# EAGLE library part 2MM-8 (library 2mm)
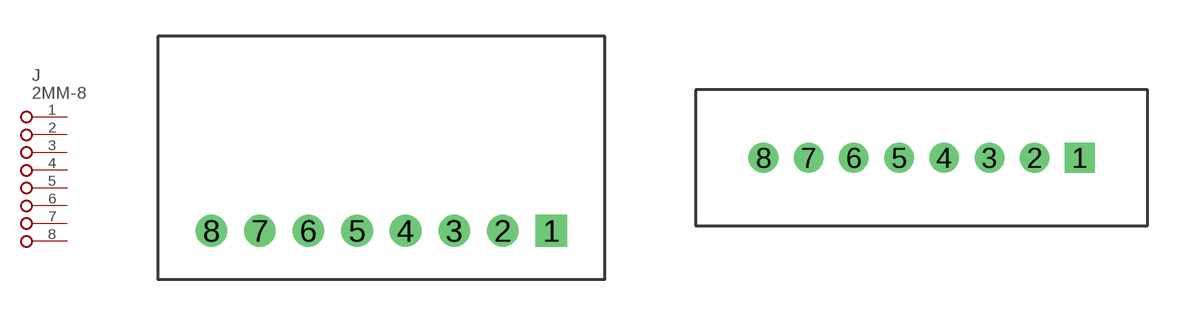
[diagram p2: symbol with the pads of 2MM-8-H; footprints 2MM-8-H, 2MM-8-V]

Designator prefix J

## 2MM-8H  [2MM-8-H]
1  1
2  2
3  3
4  4
5  5
6  6
7  7
8  8

## 2MM-8V  [2MM-8-V]
Pads as for 2MM-8-H

## Footprint 2MM-8-H (pad centres in mm)
drill 0.8 square: 1 0,0
drill 0.8 round: 2 -2,0; 3 -4,0; 4 -6,0; 5 -8,0; 6 -10,0; 7 -12,0; 8 -14,0

## Footprint 2MM-8-V (pad centres in mm)
drill 0.8 square: 1 0,0
drill 0.8 round: 2 -2,0; 3 -4,0; 4 -6,0; 5 -8,0; 6 -10,0; 7 -12,0; 8 -14,0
